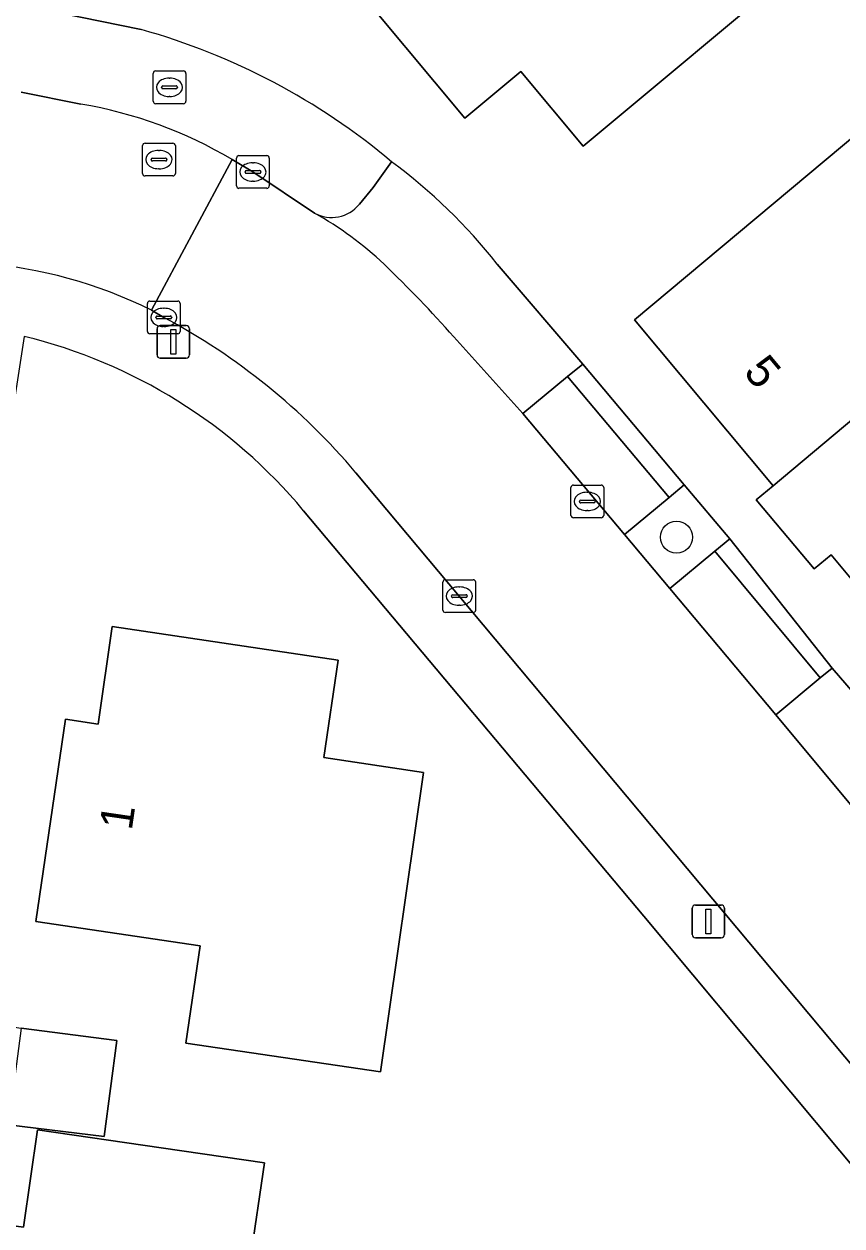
# Model space of a CAD drawing. Extents: x 164148 to 165261, y 382513 to 383432.
# Drawn here: x 164685.42 to 164710.4, y 383107.95 to 383144.67 of the extents above; entities that cross this region are included whole.
import ezdxf

# ---------------------------------------------------------------- set-up
doc = ezdxf.new("R2010")
doc.units = 0
for name, color, linetype in [('IMGEO_Boom', 7, 'Continuous'), ('IMGEO_Erf', 7, 'Continuous'), ('IMGEO_Groenvoorziening', 7, 'Continuous'), ('IMGEO_Kolk', 7, 'Continuous'), ('IMGEO_Lichtmast', 7, 'Continuous'), ('IMGEO_Pand', 7, 'Continuous'), ('IMGEO_Pand_nummerreeks', 7, 'Continuous'), ('IMGEO_Parkeervlak_open', 7, 'Continuous'), ('IMGEO_Rijbaan_lokaal_open', 7, 'Continuous'), ('IMGEO_Rioolput', 7, 'Continuous'), ('IMGEO_Voetpad_open', 7, 'Continuous')]:
    doc.layers.add(name, color=color, linetype=linetype)

msp = doc.modelspace()

# ---------------------------------------------------------------- linework, layer by layer
at = {"layer": 'IMGEO_Boom'}
msp.add_circle((164705.346, 383128.991), 0.489, dxfattribs=at)
at = {"layer": 'IMGEO_Erf'}
for points in [[(164749.279, 383118.123), (164708.585, 383168.407), (164705.154, 383172.72), (164688.93, 383159.225), (164686.54, 383144.995), (164688.997, 383144.496)], [(164699.872, 383137.335), (164702.482, 383134.278), (164705.578, 383130.586), (164706.975, 383128.938), (164710.098, 383124.992), (164715.38, 383118.866), (164718.477, 383115.168), (164719.878, 383113.513), (164722.943, 383109.809), (164728.199, 383103.519), (164731.261, 383099.826), (164732.636, 383098.167), (164735.709, 383094.481), (164741.002, 383088.171), (164744.071, 383084.462), (164745.462, 383082.828), (164748.522, 383079.109), (164753.669, 383072.954), (164756.836, 383069.153), (164758.247, 383067.473), (164761.419, 383063.672), (164766.59, 383057.489), (164769.673, 383053.79)], [(164685.42, 383135.126), (164682.705, 383117.517), (164682.279, 383114.453), (164685.334, 383113.998), (164688.257, 383113.615), (164687.868, 383110.687), (164684.941, 383111.045), (164681.864, 383111.47), (164680.372, 383101.254), (164679.477, 383095.307), (164679.334, 383094.335), (164679.22, 383092.548), (164677.944, 383082.474), (164677.674, 383082.494), (164677.503, 383081.521), (164676.599, 383075.668), (164674.064, 383058.631), (164743.462, 383048.39), (164750.216, 383047.411), (164757.629, 383053.516), (164711.831, 383108.452)], [(164711.831, 383108.452), (164704.347, 383117.418), (164693.959, 383129.801)]]:
    msp.add_lwpolyline(points, dxfattribs=at)
for points in [[(164702.499, 383140.933), (164700.592, 383143.214), (164698.886, 383141.788), (164695.223, 383146.183), (164691.237, 383150.966), (164695.132, 383154.219), (164693.195, 383156.539), (164697.789, 383160.376), (164703.728, 383153.266), (164709.288, 383146.608)], [(164711.749, 383126.441), (164710.066, 383128.454), (164709.548, 383128.021), (164707.784, 383130.13), (164708.299, 383130.562), (164704.062, 383135.626), (164712.533, 383142.712), (164716.76, 383137.659), (164722.143, 383131.224), (164717.537, 383127.387), (164715.612, 383129.698)], [(164696.304, 383112.656), (164690.359, 383113.537), (164690.799, 383116.508), (164685.777, 383117.252), (164686.683, 383123.435), (164687.684, 383123.28), (164688.111, 383126.26), (164695.018, 383125.233), (164694.576, 383122.259), (164697.618, 383121.807)], [(164694.494, 383100.363), (164692.457, 383100.642), (164692.092, 383097.977), (164688.03, 383098.534), (164688.395, 383101.199), (164683.491, 383101.872), (164684.404, 383108.045), (164685.4, 383107.912), (164685.832, 383110.885), (164689.611, 383110.336), (164692.759, 383109.878), (164692.328, 383106.91), (164695.381, 383106.466)]]:
    msp.add_lwpolyline(points, close=True, dxfattribs=at)
for centre, radius, start, end in [((164683.507, 383124.825), 20.423, 49.9527, 74.405), ((164686.367, 383126.62), 17.239, 38.4289, 53.3939), ((164681.621, 383119.524), 16.057, 39.7906, 76.3133)]:
    msp.add_arc(centre, radius, start, end, dxfattribs=at)
at = {"layer": 'IMGEO_Groenvoorziening'}
msp.add_lwpolyline([(164705.578, 383130.586), (164705.12, 383130.203), (164703.757, 383129.072), (164705.143, 383127.423), (164706.521, 383128.566), (164706.975, 383128.938)], close=True, dxfattribs=at)
at = {"layer": 'IMGEO_Kolk'}
for p, q in [((164691.985, 383140.647), (164692.837, 383140.647)), ((164691.91, 383139.721), (164691.91, 383140.573)), ((164692.398, 383140.427), (164692.423, 383140.427)), ((164692.911, 383140.573), (164692.911, 383139.721)), ((164692.169, 383140.141), (164692.169, 383140.153)), ((164692.607, 383140.104), (164692.209, 383140.104)), ((164692.212, 383140.19), (164692.61, 383140.19)), ((164692.653, 383140.153), (164692.653, 383140.141)), ((164692.837, 383139.647), (164691.985, 383139.647)), ((164692.421, 383139.867), (164692.396, 383139.867)), ((164689.188, 383135.278), (164689.188, 383136.13)), ((164689.263, 383136.204), (164690.115, 383136.204)), ((164689.676, 383135.984), (164689.701, 383135.984)), ((164690.189, 383136.13), (164690.189, 383135.278)), ((164689.447, 383135.698), (164689.447, 383135.71)), ((164689.885, 383135.661), (164689.487, 383135.661)), ((164689.49, 383135.747), (164689.888, 383135.747)), ((164689.931, 383135.71), (164689.931, 383135.698)), ((164690.115, 383135.204), (164689.263, 383135.204)), ((164689.699, 383135.424), (164689.674, 383135.424)), ((164702.123, 383129.657), (164702.123, 383130.509)), ((164702.198, 383130.583), (164703.05, 383130.583)), ((164703.124, 383130.509), (164703.124, 383129.657)), ((164702.382, 383130.077), (164702.382, 383130.089)), ((164702.82, 383130.04), (164702.422, 383130.04)), ((164702.425, 383130.126), (164702.823, 383130.126)), ((164702.611, 383130.363), (164702.636, 383130.363)), ((164702.866, 383130.089), (164702.866, 383130.077)), ((164702.634, 383129.803), (164702.609, 383129.803)), ((164703.05, 383129.583), (164702.198, 383129.583)), ((164698.212, 383126.765), (164698.212, 383127.617)), ((164698.287, 383127.691), (164699.139, 383127.691)), ((164698.7, 383127.471), (164698.725, 383127.471)), ((164699.213, 383127.617), (164699.213, 383126.765)), ((164698.471, 383127.185), (164698.471, 383127.197)), ((164698.909, 383127.148), (164698.511, 383127.148)), ((164698.514, 383127.234), (164698.912, 383127.234)), ((164698.955, 383127.197), (164698.955, 383127.185)), ((164698.723, 383126.911), (164698.698, 383126.911)), ((164699.139, 383126.691), (164698.287, 383126.691))]:
    msp.add_line(p, q, dxfattribs=at)
for points in [[(164691.985, 383140.647), (164692.837, 383140.647)], [(164691.91, 383139.721), (164691.91, 383140.573)], [(164692.911, 383140.573), (164692.911, 383139.721)], [(164692.837, 383139.647), (164691.985, 383139.647)], [(164689.188, 383135.278), (164689.188, 383136.13)], [(164689.263, 383136.204), (164690.115, 383136.204)], [(164690.189, 383136.13), (164690.189, 383135.278)], [(164690.115, 383135.204), (164689.263, 383135.204)], [(164702.123, 383129.657), (164702.123, 383130.509)], [(164702.198, 383130.583), (164703.05, 383130.583)], [(164703.124, 383130.509), (164703.124, 383129.657)], [(164703.05, 383129.583), (164702.198, 383129.583)], [(164698.212, 383126.765), (164698.212, 383127.617)], [(164698.287, 383127.691), (164699.139, 383127.691)], [(164699.213, 383127.617), (164699.213, 383126.765)], [(164699.139, 383126.691), (164698.287, 383126.691)]]:
    msp.add_lwpolyline(points, dxfattribs=at)
for centre, radius, start, end in [((164691.987, 383140.571), 0.0765, 91.552, 178.448), ((164691.987, 383140.571), 0.0765, 91.552, 178.448), ((164692.835, 383140.571), 0.0765, 1.552, 88.448), ((164692.835, 383140.571), 0.0765, 1.552, 88.448), ((164692.209, 383140.15), 0.0403, 85.8775, 175.7526), ((164692.206, 383140.14), 0.0366, 178.938, 274.7102), ((164692.61, 383140.147), 0.043, 264.8664, 352.4533), ((164692.614, 383140.152), 0.0386, 1.7309, 96.639), ((164691.987, 383139.723), 0.0765, 181.552, 268.448), ((164691.987, 383139.723), 0.0765, 181.552, 268.448), ((164692.835, 383139.723), 0.0765, 271.552, 358.448), ((164692.835, 383139.723), 0.0765, 271.552, 358.448), ((164689.265, 383136.128), 0.0765, 91.552, 178.448), ((164689.265, 383136.128), 0.0765, 91.552, 178.448), ((164690.113, 383136.128), 0.0765, 1.552, 88.448), ((164690.113, 383136.128), 0.0765, 1.552, 88.448), ((164689.487, 383135.707), 0.0403, 85.8775, 175.7526), ((164689.484, 383135.697), 0.0366, 178.938, 274.7102), ((164689.888, 383135.704), 0.043, 264.8664, 352.4533), ((164689.892, 383135.709), 0.0386, 1.7309, 96.639), ((164689.265, 383135.28), 0.0765, 181.552, 268.448), ((164689.265, 383135.28), 0.0765, 181.552, 268.448), ((164690.113, 383135.28), 0.0765, 271.552, 358.448), ((164690.113, 383135.28), 0.0765, 271.552, 358.448), ((164702.2, 383130.507), 0.0765, 91.552, 178.448), ((164702.2, 383130.507), 0.0765, 91.552, 178.448), ((164703.048, 383130.507), 0.0765, 1.552, 88.448), ((164703.048, 383130.507), 0.0765, 1.552, 88.448), ((164702.422, 383130.086), 0.0403, 85.8775, 175.7526), ((164702.419, 383130.076), 0.0366, 178.938, 274.7102), ((164702.823, 383130.083), 0.043, 264.8664, 352.4533), ((164702.827, 383130.088), 0.0386, 1.7309, 96.639), ((164702.2, 383129.659), 0.0765, 181.552, 268.448), ((164702.2, 383129.659), 0.0765, 181.552, 268.448), ((164703.048, 383129.659), 0.0765, 271.552, 358.448), ((164703.048, 383129.659), 0.0765, 271.552, 358.448), ((164698.289, 383127.615), 0.0765, 91.552, 178.448), ((164698.289, 383127.615), 0.0765, 91.552, 178.448), ((164699.137, 383127.615), 0.0765, 1.552, 88.448), ((164699.137, 383127.615), 0.0765, 1.552, 88.448), ((164698.511, 383127.194), 0.0403, 85.8775, 175.7526), ((164698.508, 383127.184), 0.0366, 178.938, 274.7102), ((164698.912, 383127.191), 0.043, 264.8664, 352.4533), ((164698.916, 383127.196), 0.0386, 1.7309, 96.639), ((164698.289, 383126.767), 0.0765, 181.552, 268.448), ((164698.289, 383126.767), 0.0765, 181.552, 268.448), ((164699.137, 383126.767), 0.0765, 271.552, 358.448), ((164699.137, 383126.767), 0.0765, 271.552, 358.448)]:
    msp.add_arc(centre, radius, start, end, dxfattribs=at)
for centre, major_axis, ratio, start_param, end_param in [((164692.397, 383140.147), (-0.387, 0.002), 0.722429, 4.712389, 7.853982), ((164692.422, 383140.147), (-0.39, 0.002), 0.717154, 1.570796, 4.712389), ((164689.675, 383135.704), (-0.387, 0.002), 0.722429, 4.712389, 7.853982), ((164689.7, 383135.704), (-0.39, 0.002), 0.717154, 1.570796, 4.712389), ((164702.61, 383130.083), (-0.387, 0.002), 0.722429, 4.712389, 7.853982), ((164702.635, 383130.083), (-0.39, 0.002), 0.717154, 1.570796, 4.712389), ((164698.699, 383127.191), (-0.387, 0.002), 0.722429, 4.712389, 7.853982), ((164698.724, 383127.191), (-0.39, 0.002), 0.717154, 1.570796, 4.712389)]:
    msp.add_ellipse(centre, major_axis=major_axis, ratio=ratio, start_param=start_param, end_param=end_param, dxfattribs=at)
at = {"layer": 'IMGEO_Lichtmast'}
for p, q in [((164689.481, 383134.558), (164689.481, 383135.358)), ((164689.481, 383135.358), (164689.481, 383134.558)), ((164689.581, 383135.458), (164690.371, 383135.458)), ((164690.371, 383135.458), (164689.581, 383135.458)), ((164690.471, 383135.358), (164690.471, 383134.558)), ((164690.471, 383134.558), (164690.471, 383135.358)), ((164690.371, 383134.458), (164689.581, 383134.458)), ((164689.581, 383134.458), (164690.371, 383134.458)), ((164705.823, 383116.855), (164705.823, 383117.655)), ((164705.823, 383117.655), (164705.823, 383116.855)), ((164705.923, 383117.755), (164706.713, 383117.755)), ((164706.713, 383117.755), (164705.923, 383117.755)), ((164706.813, 383117.655), (164706.813, 383116.855)), ((164706.813, 383116.855), (164706.813, 383117.655)), ((164706.713, 383116.755), (164705.923, 383116.755)), ((164705.923, 383116.755), (164706.713, 383116.755))]:
    msp.add_line(p, q, dxfattribs=at)
for points in [[(164689.901, 383135.333), (164690.051, 383135.333), (164690.051, 383134.583), (164689.901, 383134.583), (164689.901, 383135.333)], [(164706.243, 383117.63), (164706.393, 383117.63), (164706.393, 383116.88), (164706.243, 383116.88), (164706.243, 383117.63)]]:
    msp.add_lwpolyline(points, dxfattribs=at)
for centre, start, end in [((164689.581, 383135.358), 90, 180), ((164689.581, 383135.358), 90, 180), ((164690.371, 383135.358), 0, 90), ((164690.371, 383135.358), 360, 90), ((164689.581, 383134.558), 180, 270), ((164689.581, 383134.558), 180, 270), ((164690.371, 383134.558), 270, 0), ((164690.371, 383134.558), 270, 0), ((164705.923, 383117.655), 90, 180), ((164705.923, 383117.655), 90, 180), ((164706.713, 383117.655), 0, 90), ((164706.713, 383117.655), 360, 90), ((164705.923, 383116.855), 180, 270), ((164705.923, 383116.855), 180, 270), ((164706.713, 383116.855), 270, 0), ((164706.713, 383116.855), 270, 0)]:
    msp.add_arc(centre, 0.1, start, end, dxfattribs=at)
at = {"layer": 'IMGEO_Pand'}
for points in [[(164703.728, 383153.266), (164701.803, 383151.663), (164695.223, 383146.183), (164698.886, 383141.788), (164700.592, 383143.214), (164702.499, 383140.933), (164709.288, 383146.608)], [(164716.76, 383137.659), (164712.533, 383142.712), (164704.062, 383135.626), (164708.299, 383130.562)], [(164716.76, 383137.659), (164708.299, 383130.562), (164707.784, 383130.13), (164709.548, 383128.021), (164710.066, 383128.454), (164711.749, 383126.441), (164715.612, 383129.698), (164717.537, 383127.387), (164722.143, 383131.224)], [(164697.618, 383121.807), (164694.576, 383122.259), (164695.018, 383125.233), (164688.111, 383126.26), (164687.684, 383123.28), (164686.683, 383123.435), (164685.777, 383117.252), (164690.799, 383116.508), (164690.359, 383113.537), (164696.304, 383112.656)], [(164685.334, 383113.998), (164684.941, 383111.045), (164687.868, 383110.687), (164688.257, 383113.615)], [(164692.328, 383106.91), (164692.759, 383109.878), (164689.611, 383110.336), (164685.832, 383110.885), (164685.4, 383107.912), (164684.404, 383108.045), (164683.491, 383101.872), (164688.395, 383101.199), (164692.457, 383100.642), (164694.494, 383100.363), (164695.381, 383106.466)]]:
    msp.add_lwpolyline(points, close=True, dxfattribs=at)
at = {"layer": 'IMGEO_Parkeervlak_open'}
for points in [[(164702.016, 383133.903), (164700.649, 383132.765), (164703.757, 383129.072), (164705.12, 383130.203)], [(164706.521, 383128.566), (164705.143, 383127.423), (164708.379, 383123.561), (164709.734, 383124.699)]]:
    msp.add_lwpolyline(points, close=True, dxfattribs=at)
at = {"layer": 'IMGEO_Rijbaan_lokaal_open'}
for points in [[(164687.154, 383142.219), (164685.328, 383142.586)], [(164694.29, 383138.89), (164692.411, 383140.147), (164691.776, 383140.523), (164689.308, 383135.927), (164689.689, 383135.704)], [(164689.308, 383135.927), (164691.776, 383140.523)], [(164759.595, 383062.145), (164756.429, 383065.979), (164755.026, 383067.642), (164751.872, 383071.431), (164746.718, 383077.584), (164743.629, 383081.311), (164742.238, 383082.941), (164739.142, 383086.647), (164733.896, 383092.929), (164730.796, 383096.62), (164729.433, 383098.294), (164726.334, 383102.013), (164721.108, 383108.278), (164718.031, 383111.995), (164716.661, 383113.64), (164713.549, 383117.352), (164708.379, 383123.561), (164705.143, 383127.423), (164703.757, 383129.072), (164700.649, 383132.765), (164698.545, 383135.11)], [(164695.558, 383130.959), (164698.713, 383127.191), (164713.053, 383110.049), (164722.921, 383098.245), (164733.429, 383085.658), (164742.049, 383075.319), (164755.138, 383059.563), (164759.226, 383054.634)]]:
    msp.add_lwpolyline(points, dxfattribs=at)
for centre, radius, start, end in [((164684.947, 383129.058), 13.345, 59.2202, 80.4795), ((164688.865, 383129.279), 11.037, 46.8224, 60.5579), ((164682.978, 383123.122), 14.285, 63.6955, 85.4947), ((164670.416, 383110.24), 37.547, 41.4812, 46.1719), ((164680.217, 383117.986), 20.091, 40.2192, 61.8708)]:
    msp.add_arc(centre, radius, start, end, dxfattribs=at)
at = {"layer": 'IMGEO_Rioolput'}
for p, q in [((164689.437, 383143.233), (164690.289, 383143.233)), ((164689.362, 383142.307), (164689.362, 383143.159)), ((164689.85, 383143.013), (164689.875, 383143.013)), ((164690.363, 383143.159), (164690.363, 383142.307)), ((164689.621, 383142.727), (164689.621, 383142.739)), ((164690.059, 383142.69), (164689.661, 383142.69)), ((164689.664, 383142.776), (164690.062, 383142.776)), ((164690.105, 383142.739), (164690.105, 383142.727)), ((164690.289, 383142.233), (164689.437, 383142.233)), ((164689.873, 383142.453), (164689.848, 383142.453)), ((164689.115, 383141.025), (164689.967, 383141.025)), ((164689.04, 383140.099), (164689.04, 383140.951)), ((164689.528, 383140.805), (164689.553, 383140.805)), ((164690.041, 383140.951), (164690.041, 383140.099)), ((164689.299, 383140.519), (164689.299, 383140.531)), ((164689.737, 383140.482), (164689.339, 383140.482)), ((164689.342, 383140.568), (164689.74, 383140.568)), ((164689.783, 383140.531), (164689.783, 383140.519)), ((164689.967, 383140.025), (164689.115, 383140.025)), ((164689.551, 383140.245), (164689.526, 383140.245))]:
    msp.add_line(p, q, dxfattribs=at)
for points in [[(164689.437, 383143.233), (164690.289, 383143.233)], [(164689.362, 383142.307), (164689.362, 383143.159)], [(164690.363, 383143.159), (164690.363, 383142.307)], [(164690.289, 383142.233), (164689.437, 383142.233)], [(164689.115, 383141.025), (164689.967, 383141.025)], [(164689.04, 383140.099), (164689.04, 383140.951)], [(164690.041, 383140.951), (164690.041, 383140.099)], [(164689.967, 383140.025), (164689.115, 383140.025)]]:
    msp.add_lwpolyline(points, dxfattribs=at)
for centre, radius, start, end in [((164689.439, 383143.157), 0.0765, 91.552, 178.448), ((164689.439, 383143.157), 0.0765, 91.552, 178.448), ((164690.287, 383143.157), 0.0765, 1.552, 88.448), ((164690.287, 383143.157), 0.0765, 1.552, 88.448), ((164689.661, 383142.736), 0.0403, 85.8775, 175.7526), ((164689.658, 383142.726), 0.0366, 178.938, 274.7102), ((164690.062, 383142.733), 0.043, 264.8664, 352.4533), ((164690.066, 383142.738), 0.0386, 1.7309, 96.639), ((164689.439, 383142.309), 0.0765, 181.552, 268.448), ((164689.439, 383142.309), 0.0765, 181.552, 268.448), ((164690.287, 383142.309), 0.0765, 271.552, 358.448), ((164690.287, 383142.309), 0.0765, 271.552, 358.448), ((164689.117, 383140.949), 0.0765, 91.552, 178.448), ((164689.117, 383140.949), 0.0765, 91.552, 178.448), ((164689.965, 383140.949), 0.0765, 1.552, 88.448), ((164689.965, 383140.949), 0.0765, 1.552, 88.448), ((164689.339, 383140.528), 0.0403, 85.8775, 175.7526), ((164689.336, 383140.518), 0.0366, 178.938, 274.7102), ((164689.74, 383140.525), 0.043, 264.8664, 352.4533), ((164689.744, 383140.53), 0.0386, 1.7309, 96.639), ((164689.117, 383140.101), 0.0765, 181.552, 268.448), ((164689.117, 383140.101), 0.0765, 181.552, 268.448), ((164689.965, 383140.101), 0.0765, 271.552, 358.448), ((164689.965, 383140.101), 0.0765, 271.552, 358.448)]:
    msp.add_arc(centre, radius, start, end, dxfattribs=at)
for centre, major_axis, ratio, start_param, end_param in [((164689.849, 383142.733), (-0.387, 0.002), 0.722429, 4.712389, 7.853982), ((164689.874, 383142.733), (-0.39, 0.002), 0.717154, 1.570796, 4.712389), ((164689.527, 383140.525), (-0.387, 0.002), 0.722429, 4.712389, 7.853982), ((164689.552, 383140.525), (-0.39, 0.002), 0.717154, 1.570796, 4.712389)]:
    msp.add_ellipse(centre, major_axis=major_axis, ratio=ratio, start_param=start_param, end_param=end_param, dxfattribs=at)
at = {"layer": 'IMGEO_Voetpad_open'}
for points in [[(164688.997, 383144.496), (164686.54, 383144.995), (164686.092, 383145.085), (164685.941, 383145.116)], [(164685.328, 383142.586), (164687.154, 383142.219)], [(164691.776, 383140.523), (164692.411, 383140.147), (164694.29, 383138.89)], [(164695.664, 383139.161), (164696.079, 383139.675), (164696.647, 383140.459)], [(164696.647, 383140.459), (164696.079, 383139.675), (164695.664, 383139.161)], [(164698.545, 383135.11), (164700.649, 383132.765), (164702.016, 383133.903), (164702.482, 383134.278), (164699.872, 383137.335)], [(164689.689, 383135.704), (164689.308, 383135.927)], [(164733.429, 383085.658), (164722.921, 383098.245), (164713.053, 383110.049), (164698.713, 383127.191), (164695.558, 383130.959)], [(164693.959, 383129.801), (164704.347, 383117.418), (164711.831, 383108.452), (164757.629, 383053.516), (164759.226, 383054.634), (164755.138, 383059.563), (164742.049, 383075.319), (164733.429, 383085.658)]]:
    msp.add_lwpolyline(points, dxfattribs=at)
for points in [[(164702.482, 383134.278), (164702.016, 383133.903), (164705.12, 383130.203), (164705.578, 383130.586)], [(164706.975, 383128.938), (164706.521, 383128.566), (164709.734, 383124.699), (164710.098, 383124.992)], [(164710.098, 383124.992), (164709.734, 383124.699), (164708.379, 383123.561), (164713.549, 383117.352), (164714.919, 383118.496), (164715.38, 383118.866)]]:
    msp.add_lwpolyline(points, close=True, dxfattribs=at)
for centre, radius, start, end in [((164683.507, 383124.825), 20.423, 49.9527, 74.405), ((164684.947, 383129.058), 13.345, 59.2202, 80.4795), ((164686.367, 383126.62), 17.239, 38.4289, 53.3939), ((164694.812, 383139.861), 1.102, 241.7253, 320.5896), ((164694.812, 383139.861), 1.102, 241.7253, 320.5896), ((164688.865, 383129.279), 11.037, 46.8224, 60.5579), ((164682.978, 383123.122), 14.285, 63.6955, 85.4947), ((164670.416, 383110.24), 37.547, 41.4812, 46.1719), ((164680.217, 383117.986), 20.091, 40.2192, 61.8708), ((164681.621, 383119.524), 16.057, 39.7906, 76.3133)]:
    msp.add_arc(centre, radius, start, end, dxfattribs=at)

# ---------------------------------------------------------------- texts
at = {"layer": 'IMGEO_Pand_nummerreeks'}
for s, rotation, p in [('5', 309.9178, (164707.364, 383134.018)), ('1', 81.6637, (164688.708, 383120.011))]:
    msp.add_text(s, height=1, rotation=rotation, dxfattribs=at).set_placement(p)

doc.saveas('drawing.dxf')
